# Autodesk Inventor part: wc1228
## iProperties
Shininess: 64.0
Length Units: 11272
Angle Units: 11279
Time Units: 11290
Mass Units: 11286
Length Display Precision: 3
Angle Display Precision: 2
Compacted: True
Part Number: wc1228
Document SubType Name: Modeling
Created: 2004-08
Designer: John Blackburn
Manufacturer: Standard
Standards Organization: Custom
Density: 0.0
Volumn: 0.0
Area: 0.0
PropertySet Name: Model Information
Control State: 0
Master: False
Checked Out: False
Author: John Blackburn
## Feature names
1. Base1
